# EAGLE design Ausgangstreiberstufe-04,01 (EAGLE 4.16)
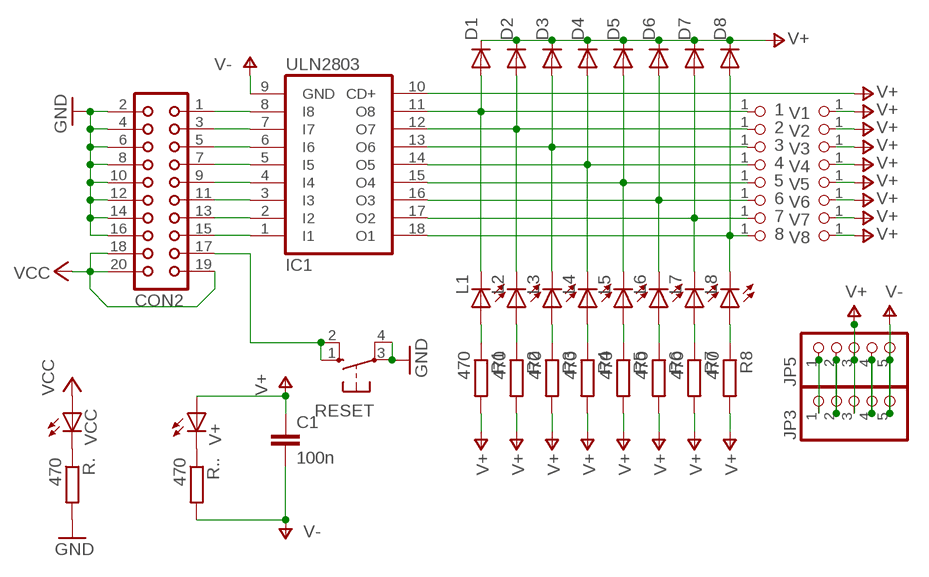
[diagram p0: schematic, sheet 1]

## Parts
1  PINHD-1X1  [1X01]
2  PINHD-1X1  [1X01]
3  PINHD-1X1  [1X01]
4  PINHD-1X1  [1X01]
5  PINHD-1X1  [1X01]
6  PINHD-1X1  [1X01]
7  PINHD-1X1  [1X01]
8  PINHD-1X1  [1X01]
C1  100n  C-EU050-030X075  [C050-030X075]
CON2  CON20  [CON20]
D1  DIODE-DO34-7  [DO34-7]
D2  DIODE-SOD61A  [SOD61A]
D3  DIODE-SOD61B  [SOD61B]
D4  DIODE-SOD61B  [SOD61B]
D5  DIODE-SOD61B  [SOD61B]
D6  DIODE-SOD61B  [SOD61B]
D7  DIODE-SOD61B  [SOD61B]
D8  DIODE-SOD61B  [SOD61B]
IC1  ULN2803  ULN2803A  [DIL18]
JP3  PINHD-1X5  [1X05]
JP5  PINHD-1X5  [1X05]
L1  LED3MM  [LED3MM]
L2  LED3MM  [LED3MM]
L3  LED3MM  [LED3MM]
L4  LED3MM  [LED3MM]
L5  LED3MM  [LED3MM]
L6  LED3MM  [LED3MM]
L7  LED3MM  [LED3MM]
L8  LED3MM  [LED3MM]
R1  470  R-EU_0204/7  [0204/7]
R2  470  R-EU_0207/10  [0207/10]
R3  470  R-EU_0207/12  [0207/12]
R4  470  R-EU_0207/15  [0207/15]
R5  470  R-EU_0207/15  [0207/15]
R6  470  R-EU_0207/15  [0207/15]
R7  470  R-EU_0207/15  [0207/15]
R8  470  R-EU_0207/15  [0207/15]
R.  470  R-EU_0204/7  [0204/7]
R..  470  R-EU_0204/7  [0204/7]
RESET  10-XX  [B3F-10XX]
V1  PINHD-1X1  [1X01]
V2  PINHD-1X1  [1X01]
V3  PINHD-1X1  [1X01]
V4  PINHD-1X1  [1X01]
V5  PINHD-1X1  [1X01]
V6  PINHD-1X1  [1X01]
V7  PINHD-1X1  [1X01]
V8  PINHD-1X1  [1X01]
V+  LED3MM  [LED3MM]
VCC  LED3MM  [LED3MM]

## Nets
GND: CON2.2 CON2.4 CON2.6 CON2.8 CON2.10 CON2.12 CON2.14 CON2.16 R..2 RESET.3(P) RESET.4(P1)
N$1: CON2.15 IC1.1(I1)
N$2: CON2.13 IC1.2(I2)
N$3: CON2.11 IC1.3(I3)
N$4: L1.A R1.1
N$6: CON2.17 RESET.1(S) RESET.2(S1)
N$7: JP3.2 JP5.2
N$9: L2.A R2.1
N$10: L3.A R3.1
N$14: CON2.9 IC1.4(I4)
N$15: CON2.7 IC1.5(I5)
N$16: JP3.4 JP5.4
N$17: CON2.5 IC1.6(I6)
N$18: CON2.3 IC1.7(I7)
N$19: CON2.1 IC1.8(I8)
N$21: 1.1 D1.A IC1.11(O8) L1.K(C)
N$22: 2.1 D2.A IC1.12(O7) L2.K(C)
N$23: 3.1 D3.A IC1.13(O6) L3.K(C)
N$24: 4.1 D4.A IC1.14(O5) L4.K(C)
N$25: 5.1 D5.A IC1.15(O4) L5.K(C)
N$26: 6.1 D6.A IC1.16(O3) L6.K(C)
N$27: 7.1 D7.A IC1.17(O2) L7.K(C)
N$28: 8.1 D8.A IC1.18(O1) L8.K(C)
N$29: L4.A R4.1
N$30: JP3.1 JP5.1
N$31: L5.A R5.1
N$32: L6.A R6.1
N$33: L7.A R7.1
N$34: L8.A R8.1
N$35: R..1 VCC.K(C)
N$36: R...1 V+.K(C)
V+: C1.1 D1.C D2.C D3.C D4.C D5.C D6.C D7.C D8.C IC1.10(CD+) JP3.3 JP5.3 R1.2 R2.2 R3.2 R4.2 R5.2 R6.2 R7.2 R8.2 V1.1 V2.1 V3.1 V4.1 V5.1 V6.1 V7.1 V8.1 V+.A
V-: C1.2 IC1.9(GND) JP3.5 JP5.5 R...2
VCC: CON2.18 CON2.19 CON2.20 VCC.A

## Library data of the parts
1-8 V1-V8 = pinhead 02:PINHD-1X1: PIN HEADER
C1 = rcl:C-EU: CAPACITOR, European symbol
CON2 = con-harting:CON20: CONNECTOR
D1-D8 = diode:DIODE-: DIODE
IC1 = uln-udn:ULN2803A: DRIVER ARRAY
JP3 JP5 = pinhead:PINHD-1X5: PIN HEADER
L1-L8 V+ VCC = led:LED: LED
R1-R8 R. R.. = rcl:R-EU_: RESISTOR, European symbol
RESET = switch-omron:10-XX: OMRON SWITCH

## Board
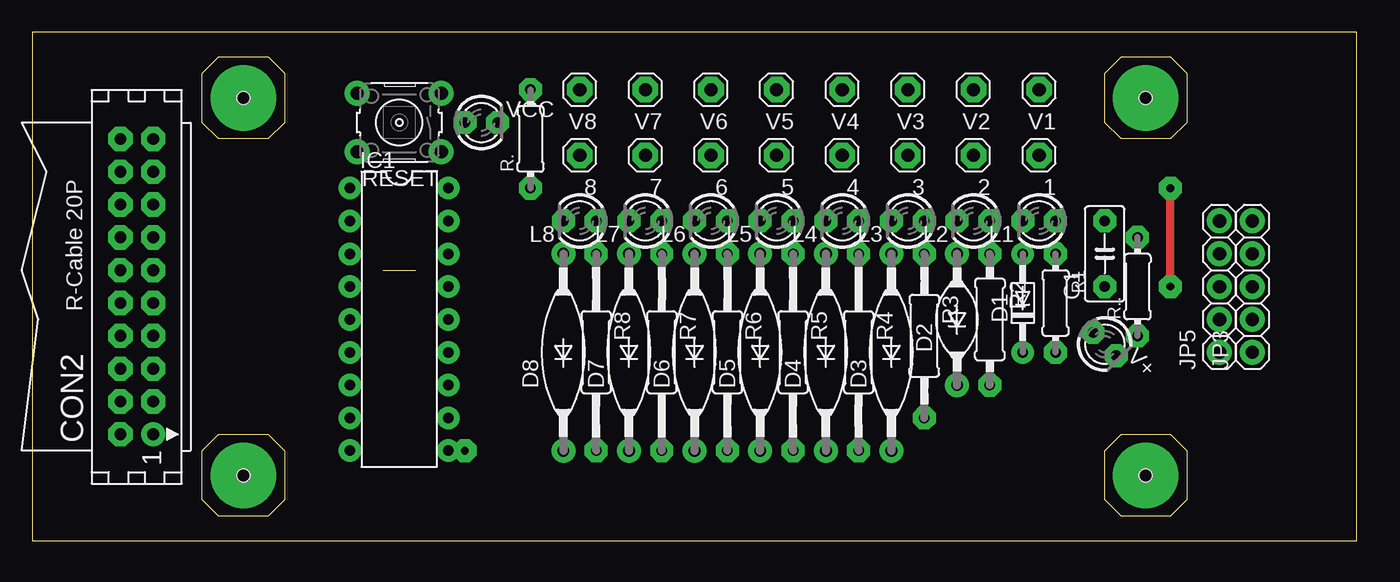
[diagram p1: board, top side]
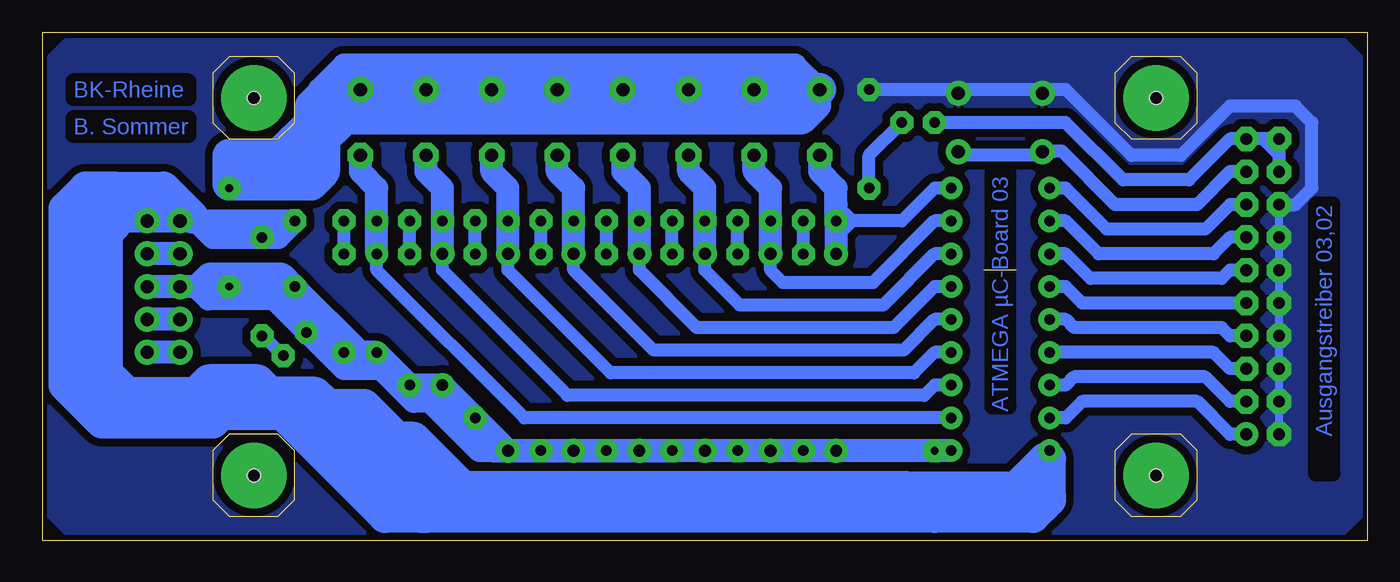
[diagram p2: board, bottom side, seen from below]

Size 102.54 x 39.36 mm. Coordinates in mm from the lower left corner, seen from the top.
Outline: 27.14,20.95 29.68,20.95
Outline: 0,0 102.54,0 102.54,39.36 0,39.36 0,0
Outline: 14.44,37.46 18.25,37.46 19.52,36.19 19.52,32.38 18.25,31.11 14.44,31.11 13.17,32.38 13.17,36.19 14.44,37.46
Outline: 14.44,8.25 18.25,8.25 19.52,6.98 19.52,3.17 18.25,1.9 14.44,1.9 13.17,3.17 13.17,6.98 14.44,8.25
Outline: 84.29,37.46 88.1,37.46 89.37,36.19 89.37,32.38 88.1,31.11 84.29,31.11 83.02,32.38 83.02,36.19 84.29,37.46
Outline: 84.29,8.25 88.1,8.25 89.37,6.98 89.37,3.17 88.1,1.9 84.29,1.9 83.02,3.17 83.02,6.98 84.29,8.25
Copper layers (1*16): Top 0.035mm / dielectric 1.5mm / Bottom 0.035mm
Design rules "default": minimum track width 24mil, minimum drill 0.5mm, track to track 24mil, track to pad 24mil, pad to pad 24mil, via to via 24mil, smd to smd 0mil, copper to edge 0mil, drill to drill 1mil, minimum pad ring 19mil, minimum via ring 19mil, stop-mask expansion 4mil, vias tented up to drill 0mil, thermal gap 0mil
Holes 1.02 mm at 16.34,34.29 16.34,5.08 86.19,34.29 86.19,5.08

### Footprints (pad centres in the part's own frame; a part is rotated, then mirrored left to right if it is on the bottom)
1X01 = drill 1.016 octagon: 1 0,0
C050-030X075 = drill 0.813 octagon: 1 -2.54,0; 2 2.54,0
CON20 = drill 0.914 round: 1 -11.43,-1.27 | drill 0.914 octagon: 2 -11.43,1.27; 3 -8.89,-1.27; 4 -8.89,1.27; 5 -6.35,-1.27; 6 -6.35,1.27; 7 -3.81,-1.27; 8 -3.81,1.27; 9 -1.27,-1.27; 10 -1.27,1.27; 11 1.27,-1.27; 12 1.27,1.27; 13 3.81,-1.27; 14 3.81,1.27; 15 6.35,-1.27; 16 6.35,1.27; 17 8.89,-1.27; 18 8.89,1.27; 19 11.43,-1.27; 20 11.43,1.27
DO34-7 = drill 0.813 long: A 3.81,0; C -3.81,0
SOD61A = drill 0.914 long: A 5.08,0; C -5.08,0
SOD61B = drill 0.914 long: A 7.62,0; C -7.62,0
DIL18 = drill 0.813 long: 1 -10.16,-3.81; 2 -7.62,-3.81; 3 -5.08,-3.81; 4 -2.54,-3.81; 5 0,-3.81; 6 2.54,-3.81; 7 5.08,-3.81; 8 7.62,-3.81; 9 10.16,-3.81; 10 10.16,3.81; 11 7.62,3.81; 12 5.08,3.81; 13 2.54,3.81; 14 0,3.81; 15 -2.54,3.81; 16 -5.08,3.81; 17 -7.62,3.81; 18 -10.16,3.81
1X05 = drill 1.016 long: 1 -5.08,0; 2 -2.54,0; 3 0,0; 4 2.54,0; 5 5.08,0
LED3MM = drill 0.813 octagon: A -1.27,0; K 1.27,0
0204/7 = drill 0.813 octagon: 1 -3.81,0; 2 3.81,0
0207/10 = drill 0.813 octagon: 1 -5.08,0; 2 5.08,0
0207/12 = drill 0.813 octagon: 1 -6.35,0; 2 6.35,0
0207/15 = drill 0.813 octagon: 1 -7.62,0; 2 7.62,0
B3F-10XX = drill 1.016 long: 1 -3.251,2.261; 2 3.251,2.261; 3 -3.251,-2.261; 4 3.251,-2.261

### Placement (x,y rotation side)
1  77.94,29.84 180 top
2  72.86,29.84 180 top
3  67.78,29.84 180 top
4  62.7,29.84 180 top
5  57.62,29.84 180 top
6  52.54,29.84 180 top
7  47.46,29.84 180 top
8  42.38,29.84 180 top
C1  83.02,22.22 90 top
CON2  8.09,19.68 90 top
D1  76.67,18.41 90 top
D2  71.59,17.14 90 top
D3  66.51,14.6 90 top
D4  61.43,14.6 90 top
D5  56.35,14.6 90 top
D6  51.27,14.6 90 top
D7  46.19,14.6 90 top
D8  41.11,14.6 90 top
IC1  28.41,17.14 270 top
JP3  94.45,19.68 90 top
JP5  91.91,19.68 90 top
L1  77.94,24.76 180 top
L2  72.86,24.76 180 top
L3  67.78,24.76 180 top
L4  62.7,24.76 180 top
L5  57.62,24.76 180 top
L6  52.54,24.76 180 top
L7  47.46,24.76 180 top
L8  42.38,24.76 180 top
R1  79.21,18.41 270 top
R2  74.13,17.14 270 top
R3  69.05,15.87 270 top
R4  63.97,14.6 270 top
R5  58.89,14.6 270 top
R6  53.81,14.6 270 top
R7  48.73,14.6 270 top
R8  43.65,14.6 270 top
R.  38.57,31.11 90 top
R..  85.56,19.68 90 top
RESET  28.41,32.38 180 top
V1  77.94,34.92 180 top
V2  72.86,34.92 180 top
V3  67.78,34.92 180 top
V4  62.7,34.92 180 top
V5  57.62,34.92 180 top
V6  52.54,34.92 180 top
V7  47.46,34.92 180 top
V8  42.38,34.92 180 top
V+  83.02,15.24 315 top
VCC  34.76,32.38 0 top

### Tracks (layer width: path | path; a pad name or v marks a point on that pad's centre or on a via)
GND
  Bottom 0.61: CON2.16 CON2.14 CON2.12 CON2.10 CON2.8 CON2.6 CON2.4 CON2.2
  Bottom 1.016: CON2.16 5.55,26.03 4.28,27.3 4.28,32.38 5.55,33.65 10.63,33.65 14.44,29.84 18.25,29.84 23.33,34.92 24.88,34.92 RESET.4 25.44,34.92 31.38,34.92 RESET.3 31.94,34.64 32.22,34.92 R..2
  pour Bottom: 1.74,38.73 100.8,38.73 102.07,37.46 101.75,1.9 100.48,0.63 1.74,0.63 0.47,1.9 0.47,37.46
N$1
  Bottom 1.016: CON2.15 10.63,26.03 12.54,24.12 20.15,24.12 23.33,27.3 IC1.1
N$2
  Bottom 1.016: CON2.13 10.63,23.49 11.9,22.22 20.79,22.22 23.33,24.76 IC1.2
N$3
  Bottom 1.016: CON2.11 10.63,20.95 11.27,20.31 21.42,20.31 23.33,22.22 IC1.3
N$4
  Bottom 1.016: R1.1 L1.A
N$6
  Bottom 1.016: CON2.17 10.63,28.57 13.17,26.03 19.52,26.03 23.65,30.16 24.28,30.16 24.24,30.12 RESET.2 25.44,29.84 31.38,29.84 RESET.1
N$7
  Bottom 1.778: JP5.2 JP3.2
N$8  (via drill 0.6 pad 5.08)
  other vias: 16.34,34.29
N$9
  Bottom 1.016: R2.1 L2.A
N$10
  Bottom 1.016: R3.1 L3.A
N$11  (via drill 0.6 pad 5.08)
  other vias: 16.34,5.08
N$12  (via drill 0.6 pad 5.08)
  other vias: 86.19,5.08
N$13  (via drill 0.6 pad 5.08)
  other vias: 86.19,34.29
N$14
  Bottom 1.016: CON2.9 22.06,18.41 23.33,19.68 IC1.4
N$15
  Bottom 1.016: CON2.7 10.63,15.87 11.27,16.5 22.7,16.5 23.33,17.14 IC1.5
N$16
  Bottom 1.778: JP5.4 JP3.4
N$17
  Bottom 1.016: CON2.5 10.63,13.33 11.9,14.6 IC1.6
N$18
  Bottom 1.016: CON2.3 10.63,10.79 12.54,12.7 22.7,12.7 23.33,12.06 IC1.7
N$19
  Bottom 1.016: IC1.8 23.33,9.52 22.06,10.79 13.17,10.79 10.63,8.25 CON2.1
N$21
  Bottom 1.016: IC1.11 65.24,9.52 76.67,20.95 D1.A
  Bottom 1.778: 1.1 77.94,28.57 76.67,27.3 L1.K D1.A
N$22
  Bottom 1.016: IC1.12 33.49,12.06 34.28,11.27 61.91,11.27 71.59,20.95 D2.A
  Bottom 1.778: 2.1 72.86,28.57 71.59,27.3 L2.K D2.A
N$23
  Bottom 1.016: IC1.13 33.49,14.6 35.08,13.01 58.57,13.01 66.51,20.95 D3.A
  Bottom 1.778: 3.1 67.78,28.57 66.51,27.3 L3.K D3.A
N$24
  Bottom 1.016: IC1.14 33.49,17.14 35.87,14.76 55.24,14.76 61.43,20.95 D4.A
  Bottom 1.778: 4.1 62.7,28.57 61.43,27.3 L4.K D4.A
N$25
  Bottom 1.016: IC1.15 33.49,19.68 36.66,16.5 51.91,16.5 56.35,20.95 D5.A
  Bottom 1.778: 5.1 57.62,28.57 56.35,27.3 L5.K D5.A
N$26
  Bottom 1.016: IC1.16 33.49,22.22 37.46,18.25 48.57,18.25 51.27,20.95 D6.A
  Bottom 1.778: 6.1 52.54,28.57 51.27,27.3 L6.K D6.A
N$27
  Bottom 1.016: IC1.17 33.49,24.76 38.25,20 45.24,20 46.19,20.95 D7.A
  Bottom 1.778: 7.1 47.46,28.57 46.19,27.3 L7.K D7.A
N$28
  Bottom 1.016: D8.A L8.K 39.84,24.76 | IC1.18 33.49,27.3 36.03,24.76 39.84,24.76 | 39.84,24.76 41.11,23.49 | 39.84,24.76 41.11,26.03
  Bottom 1.778: 8.1 42.38,28.57 41.11,27.3 41.11,26.03 L8.K 41.11,23.49 D8.A
N$29
  Bottom 1.016: R4.1 L4.A
N$30
  Bottom 1.778: JP5.1 JP3.1
N$31
  Bottom 1.016: R5.1 L5.A
N$32
  Bottom 1.016: R6.1 L6.A
N$33
  Bottom 1.016: R7.1 L7.A
N$34
  Bottom 1.016: R8.1 L8.A
N$35
  Bottom 1.016: VCC.K 38.57,29.84 R..1
N$36
  Bottom 1.016: V+.K 85.45,15.87 R...1
N$37
  pour Bottom: 0.47,37.46 1.74,38.73 100.8,38.73 102.07,37.46 102.07,1.9 100.8,0.63 1.74,0.63 0.47,1.9
V+  (via drill 0.6 pad 1.78)
  Top 0.61: v88.1,19.68 v88.1,27.3
  Bottom 1.016: V+.A 81.75,16.5 81.75,16.82
  Bottom 1.778: V8.1 V7.1 V6.1 V5.1 V4.1 V3.1 V2.1 75.4,34.92 | 75.4,34.92 V1.1 | 75.4,32.38 43.65,32.38 42.38,33.65 | 77.94,33.65 42.38,33.65 | 77.94,33.65 76.67,32.38 | 75.4,32.38 75.4,34.92 | IC1.10 v33.49,6.98 | 75.4,34.92 75.4,33.65 76.67,32.38 | 76.67,32.38 75.4,32.38 | 80.48,32.38 79.53,32.38 76.67,32.38 | 80.48,32.38 79.21,33.65 77.94,33.65 | 36.66,6.98 D8.C R8.2 D7.C R7.2 D6.C R6.2 D5.C R5.2 D4.C R4.2 D3.C | D3.C R3.2 D2.C R2.2 D1.C | v33.49,6.98 36.66,6.98 | 36.66,6.98 67.78,6.98 | 67.78,6.98 68.73,6.98 72.54,10.79 | 67.78,6.98 D3.C | 67.78,6.98 71.59,10.79 72.54,10.79 | 72.54,10.79 73.81,10.79 76.35,13.33 79.21,13.33 | 79.21,13.33 R1.2 | 79.21,13.33 83.02,17.14 | 83.02,17.14 83.02,18.73 | C1.1 83.02,18.73 | D1.C 77.94,14.6 C1.1 | D1.C 77.94,13.33 R1.2 | R1.2 81.59,16.98 81.75,17.14 83.02,17.14 | 83.02,17.14 84.61,18.73 | 83.02,18.73 84.61,18.73 | 84.61,18.73 89.69,18.73 90.64,19.68 | C1.1 v88.1,19.68 | v88.1,19.68 90.64,19.68 | 90.64,19.68 JP5.3 JP3.3 | C1.1 83.97,20.63 89.69,20.63 90.64,19.68 | v88.1,27.3 85.56,27.3 80.48,32.38 | C1.1 v88.1,19.68 | 42.38,33.65 V8.1 | v33.49,6.98 33.81,6.98 | V8.1 44.28,36.83 79.21,36.83 81.11,34.92
  Bottom 2.54: 77.62,34.6 V1.1 80.48,34.92 | 81.59,16.98 81.75,16.82 81.75,17.46 | 81.59,16.98 | 80.48,34.92 81.75,33.65 81.75,32.38 | 81.75,32.38 81.75,31.74 82.07,31.43 | 82.07,31.43 85.56,27.93 83.02,27.93 | 83.02,27.93 82.07,28.89 82.07,31.43 | 81.75,28.57 82.39,28.57 83.02,27.93 | 83.02,27.93 81.43,27.93 80.8,28.57 | 80.8,28.57 80.8,31.11 79.53,32.38 | 85.56,29.84 85.56,28.57 | 85.56,29.84 88.1,29.84 88.1,27.62 81.75,27.62 80.8,28.57 | 85.56,29.84 84.29,29.84 81.75,32.38 | V8.1 80.48,34.92
V-
  Bottom 1.016: 85.56,24.76 R...2
  Bottom 1.778: 24.6,3.49 24.6,6.34 IC1.9 | 90.64,24.76 JP5.5 JP3.5 96.99,24.76 | 90.64,24.76 85.56,24.76 C1.2 84.29,23.49 89.37,23.49 90.64,24.76
  Bottom 2.54: 24.6,3.17 25.23,2.54 70.64,2.54 73.81,5.71 75.4,5.71 77.94,8.25 80.48,8.25 83.02,10.79 83.34,10.79 | 24.6,3.17 24.6,3.49 | 83.34,10.79 95.72,10.79 96.67,11.74 | 96.67,11.74 98.26,13.33 98.26,14.6 | 98.26,14.6 98.26,23.49 96.99,24.76 | 24.6,3.17 25.87,1.9 33.49,1.9 | 33.49,1.9 72.86,1.9 | 72.86,1.9 73.18,1.9 76.67,5.39 78.26,5.39 79.84,6.98 81.11,6.98 | 81.11,6.98 83.97,9.84 88.73,9.84 89.37,9.2 94.77,9.2 | 94.77,9.2 98.26,12.7 98.26,13.01 | 96.99,24.76 98.26,24.76 99.53,23.49 | 99.53,13.33 99.53,23.49 | 95.4,9.2 99.53,13.33 | 99.53,13.33 99.53,10.79 98.58,9.84 | 98.58,9.84 97.94,9.2 95.4,9.2 | 94.77,9.2 95.4,9.2 | 33.49,1.9 35.71,4.12 37.94,4.12 | 37.94,4.12 70,4.12 73.81,7.93 75.08,7.93 | 75.08,7.93 75.72,7.93 | 75.08,7.93 77.62,10.47 80.48,10.47 80.8,10.79 | 99.53,23.49 96.99,26.03 91.91,26.03 | 91.91,26.03 90.96,25.08 | 91.91,26.03 93.18,27.3 96.99,27.3 | 99.53,24.76 96.99,27.3 | 99.53,23.49 99.53,24.76 | 83.34,10.79 80.8,10.79 | 80.8,10.79 81.43,11.43 84.92,11.43 85.88,12.38 89.69,12.38 90.64,11.43 96.04,11.43 | 96.04,11.43 96.36,11.43 96.67,11.74 | 99.53,24.76 100.8,23.49 100.8,22.86 | 100.8,22.86 100.8,12.06 98.58,9.84 | 37.94,4.12 27.14,4.12 24.92,6.34 | 24.6,3.17 24.6,6.34 | 72.86,1.9 76.03,1.9 81.11,6.98 | 96.99,27.3 99.21,27.3 100.8,25.71 100.8,22.86 | 96.99,24.76 96.99,24.44 97.62,23.81 97.62,12.38 | 98.26,14.6 98.26,13.65 96.04,11.43
VCC
  Bottom 1.016: 8.09,31.11 CON2.20 6.82,29.84 | CON2.18 6.82,29.84 | 6.82,29.84 8.09,31.11 | 8.09,31.11 CON2.19 10.63,31.11 13.81,27.93 18.88,27.93 23.33,32.38 VCC.A

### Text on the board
Bottom: BK-Rheine | B. Sommer | ATMEGA µC-Board 03 | Ausgangstreiber 03,02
